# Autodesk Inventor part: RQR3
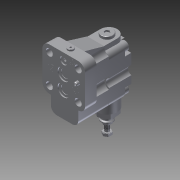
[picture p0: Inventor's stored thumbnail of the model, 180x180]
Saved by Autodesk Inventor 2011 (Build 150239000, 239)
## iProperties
Created: 2012-01
Part Number: RQR3
Document SubType Name: Modeling
Designer: khramov
Density: 1 g/cm^3
Author: khramov
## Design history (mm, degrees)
derived "RQR331.iam"
node "Твердое тело1"
node "0112481.ipt:1"
sketch "0550326.ipt:1"
sketch "0112484.ipt:1"
sketch "0571501.ipt:1"
sketch "0119296.ipt:1"
sketch "0530544.ipt:1"
sketch "0530329_ISO_24017___M8x40.ipt:1"
sketch "0530083_UNI_5931___M10x45.ipt:1"
sketch "0530083_UNI_5931___M10x45.ipt:2"
sketch "0530083_UNI_5931___M10x45.ipt:3"
sketch "0530083_UNI_5931___M10x45.ipt:4"
